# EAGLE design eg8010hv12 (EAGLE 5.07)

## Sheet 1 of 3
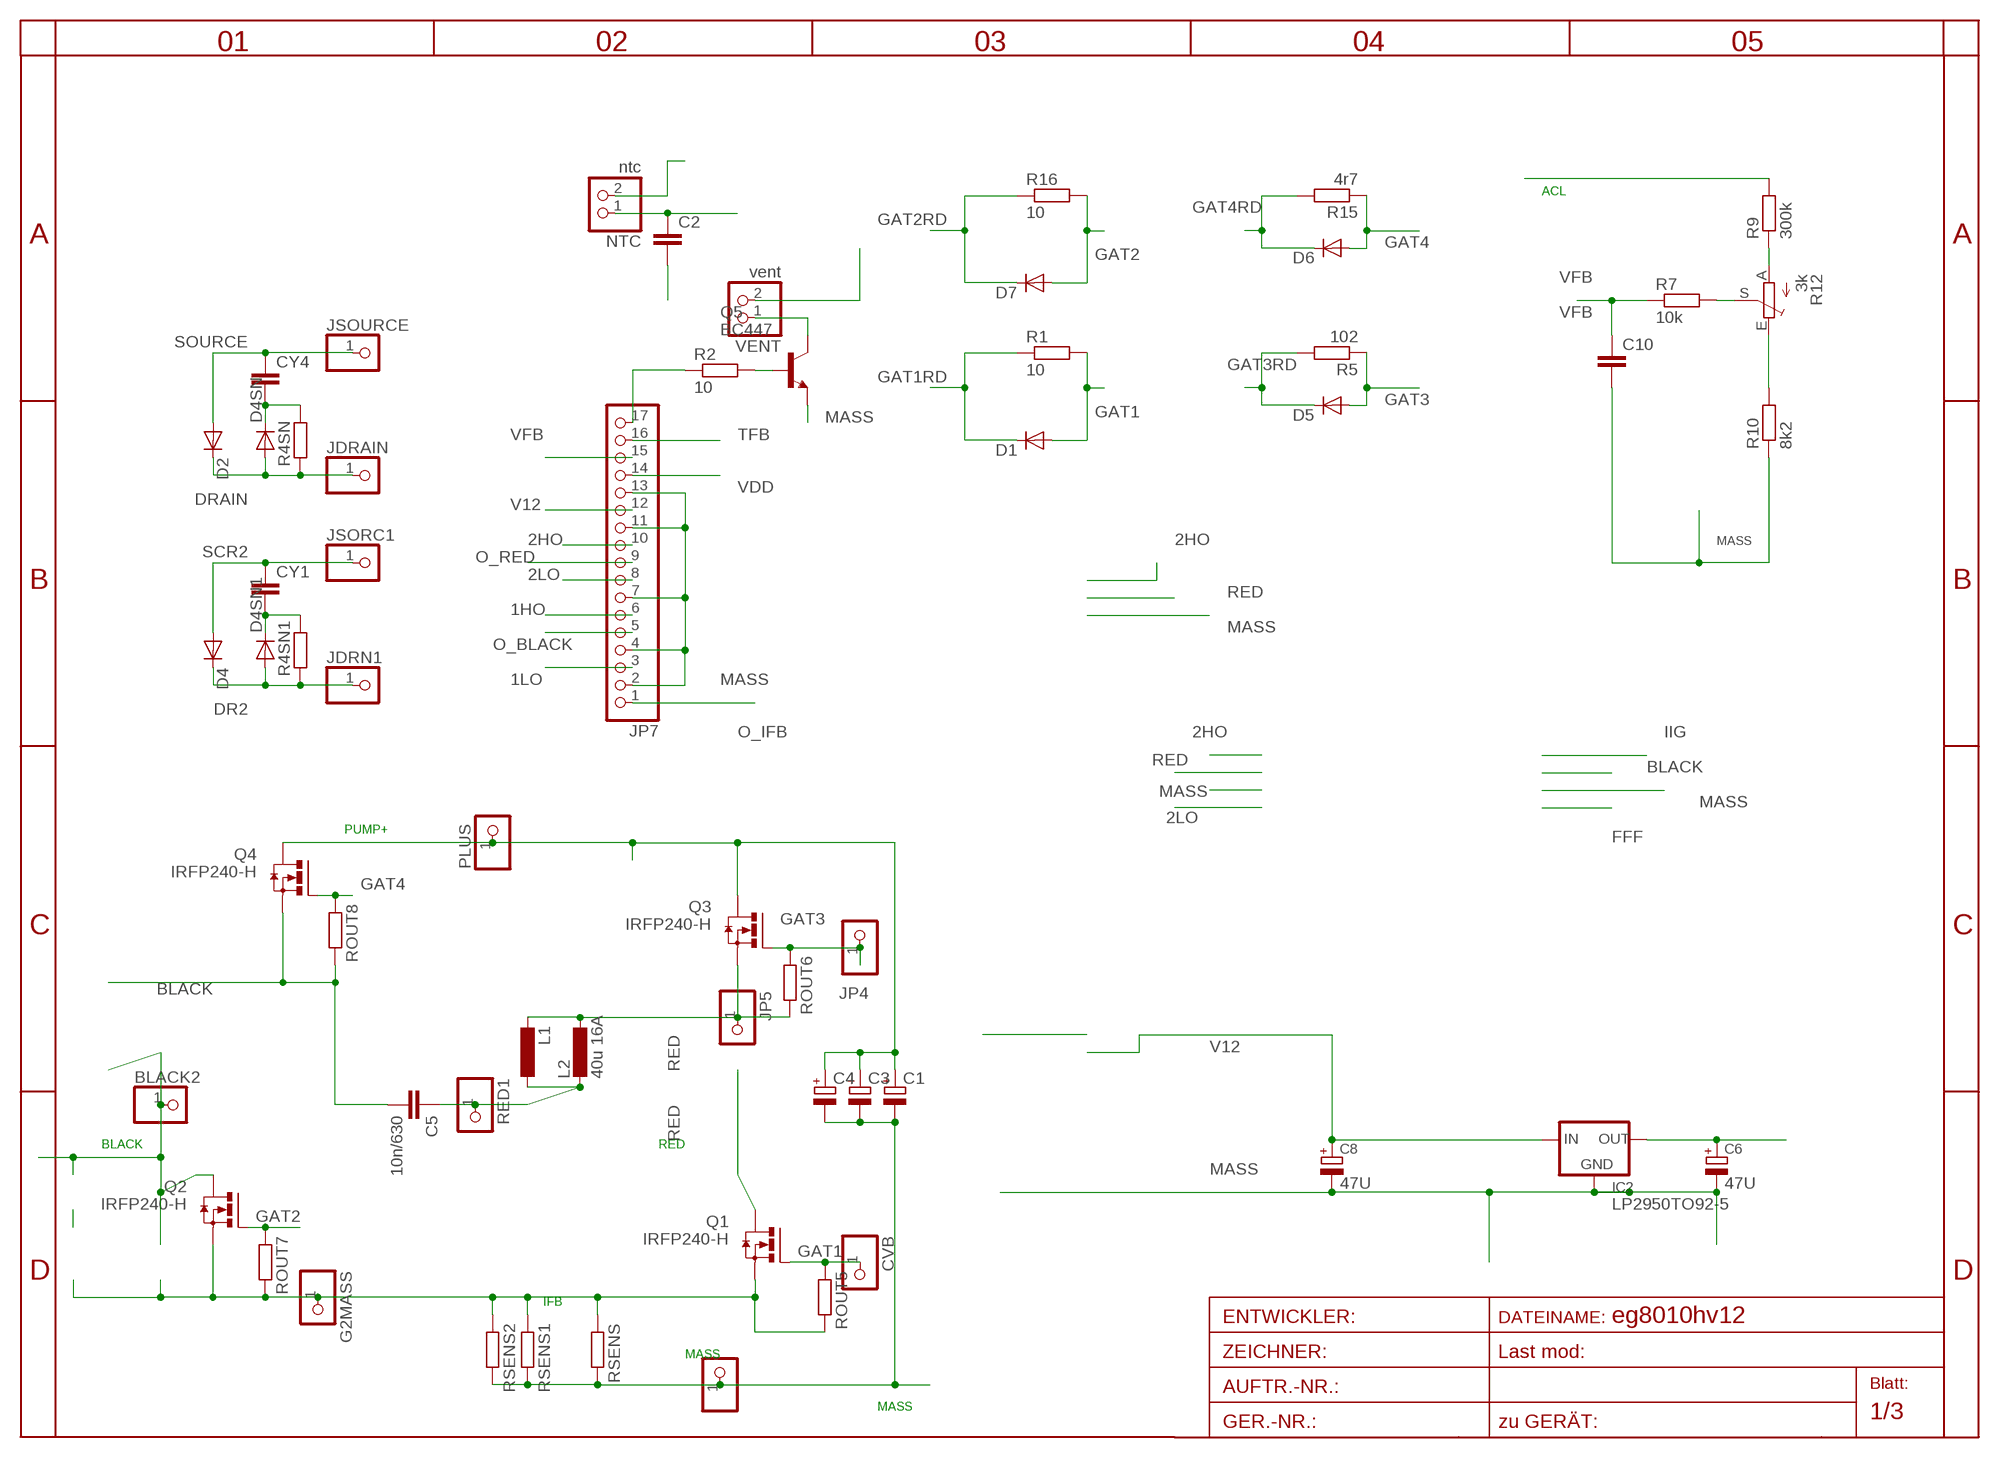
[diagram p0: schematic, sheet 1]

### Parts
BLACK2  PINHD-1X12MM3  [1X2MM3]
C1  CPOL-EUE5-13  [E5-13]
C2  C-EUC1206  [C1206]
C3  CPOL-EUE5-13  [E5-13]
C4  CPOL-EUE5-13  [E5-13]
C5  10n/630  C-EU275-173X316  [C275-173X316]
C6  47U  CPOL-EUE2.5-6  [E2,5-6]
C8  47U  CPOL-EUE2.5-6  [E2,5-6]
C10  C-EUC0805  [C0805]
CVB  PINHD-1X11MM0  [1X1MM0]
CY1  CXXC10B5  [XC10B5]
CY4  CXXC10B5  [XC10B5]
D1  DIODE-SMA-DO214  [SMA-DO214AC]
D2  DIODE-SMC  [SMC]
D4  DIODE-SMC  [SMC]
D4SN  DIODE-P1-10  [P1-10]
D4SN1  DIODE-P1-10  [P1-10]
D5  DIODE-MINIMELF  [MINIMELF]
D6  DIODE-SMA-DO214  [SMA-DO214AC]
D7  DIODE-SMA-DO214  [SMA-DO214AC]
G2MASS  PINHD-1X11MM0  [1X1MM0]
IC2  LP2950TO92-5  [T092-5]
JDRAIN  PINHD-1X11MM0  [1X1MM0]
JDRN1  PINHD-1X11MM0  [1X1MM0]
JP4  PINHD-1X11MM0  [1X1MM0]
JP5  PINHD-1X11MM0  [1X1MM0]
JP7  PINHD-1X17  [1X17]
JSORC1  PINHD-1X11MM0  [1X1MM0]
JSOURCE  PINHD-1X11MM0  [1X1MM0]
L1  L-EU4.13  [0204/13]
L2  40u 16A  L-EURNG  [RING]
MINUS  PINHD-1X12MM3  [1X2MM3]
NTC  ntc  PINHD-1X2STR  [1X02]
PLUS  PINHD-1X12MM3  [1X2MM3]
Q1  IRFP240-H  [TO247BH]
Q2  IRFP240-H  [TO247BH]
Q3  IRFP240-H  [TO247BH]
Q4  IRFP240-H  [TO247BH]
Q5  BC447  [TO92-EBC]
R1  10  R-EU_R1206  [R1206]
R2  10  R-EU_R0805  [R0805]
R4SN  R-EU_0207/10  [0207/10]
R4SN1  R-EU_0207/10  [0207/10]
R5  102  R-EU_R1206  [R1206]
R7  10k  R-EU_R0805  [R0805]
R9  300k  R-EU_0207/40  [0207/40]
R10  8k2  R-EU_R0805  [R0805]
R12  3k  TRIM_EU-CA6V  [CA6V]
R15  4r7  R-EU_0411/15  [0411/15]
R16  10  R-EU_R1206  [R1206]
RED1  PINHD-1X12MM3  [1X2MM3]
ROUT5  R-EU_0207/10  [0207/10]
ROUT6  R-EU_0207/10  [0207/10]
ROUT7  R-EU_0207/10  [0207/10]
ROUT8  R-EU_0207/10  [0207/10]
RSENS  R-EU_0204/7  [0204/7]
RSENS1  R-EU_0204/7  [0204/7]
RSENS2  R-EU_0922V  [0922V]
VENT  vent  PINHD-1X2STR  [1X02]

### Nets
1HO: JP7.6 ; also sheet 3
1LO: JP7.3 ; also sheet 3
2HO: JP7.10 ; also sheet 3
2LO: JP7.8 ; also sheet 3
ACL: C5.1 L1.1 L2.2 R9.2 RED1.1
BLACK: BLACK2.1 C5.2 Q2.D Q4.S ROUT8.2 ; also sheet 3
DR2: D4.C D4SN1.A JDRN1.1 R4SN1.1
DRAIN: D2.C D4SN.A JDRAIN.1 R4SN.1
GAT1: CVB.1 D1.A Q1.G R1.2 ROUT5.1
GAT1RD: D1.K(C) R1.1 ; also sheet 3
GAT2: D7.A Q2.G R16.2 ROUT7.1
GAT2RD: D7.K(C) R16.1 ; also sheet 3
GAT3: D5.A JP4.1 Q3.G R5.1 ROUT6.1
GAT3RD: D5.C R5.2 ; also sheet 3
GAT4: D6.A Q4.G R15.1 ROUT8.1
GAT4RD: D6.K(C) R15.2 ; also sheet 3
IFB: G2MASS.1 Q1.S Q2.S ROUT5.2 ROUT7.2 RSENS1.1 RSENS2.1 RSENS.1 ; also sheet 3
MASS: C1.- C2.2 C3.- C4.- C6.- C8.- C10.2 IC2.2(GND) JP7.2 JP7.4 JP7.7 JP7.11 JP7.13 MINUS.1 Q5.E R10.1 RSENS1.2 RSENS2.2 RSENS.2 ; also sheet 2,3
N$1: Q5.C VENT.1
N$2: Q5.B R2.2
N$3: JP7.17 R2.1
N$29: R10.2 R12.E
N$30: R9.1 R12.A
N$31: R7.2 R12.S
O_BLACK: JP7.5
O_IFB: JP7.1 ; also sheet 3
O_RED: JP7.9
PUMP+: C1.+ C3.+ C4.+ PLUS.1 Q3.D Q4.D ; also sheet 2
RED: JP5.1 L1.2 L2.1 Q1.D Q3.S ROUT6.2 ; also sheet 3
SCR2: CY1.1 D4.A JSORC1.1
SNUB1: CY1.2 D4SN1.C R4SN1.2
SNUB2: CY4.2 D4SN.C R4SN.2
SOURCE: CY4.1 D2.A JSOURCE.1
TFB: C2.1 JP7.16 NTC.1
V12: C8.+ IC2.3(IN) JP7.12 ; also sheet 2,3
VDD: C6.+ IC2.1(OUT) JP7.14 NTC.2 VENT.2
VFB: C10.1 JP7.15 R7.1

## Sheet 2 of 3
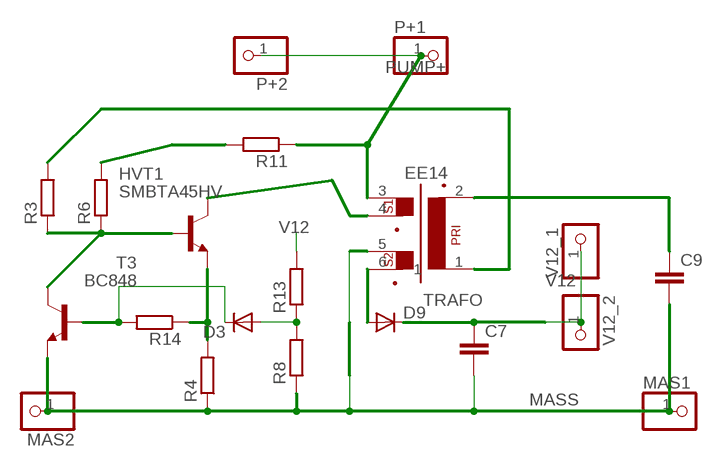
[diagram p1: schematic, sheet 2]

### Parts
C7  C-EUC1206  [C1206]
C9  C-EUC0805  [C0805]
D3  DIODE-MINIMELF  [MINIMELF]
D9  DIODE-SMA-DO214  [SMA-DO214AC]
HVT1  SMBTA45HV  [SOT23HV]
MAS1  PINHD-1X11X0.4  [1X01]
MAS2  PINHD-1X11X0.4  [1X01]
P+1  PINHD-1X11X0.4  [1X01]
P+2  PINHD-1X11X0.4  [1X01]
R3  R-EU_R0805  [R0805]
R4  R-EU_R0805  [R0805]
R6  R-EU_R1206  [R1206]
R8  R-EU_R0805  [R0805]
R11  R-EU_R1206  [R1206]
R13  R-EU_R0805  [R0805]
R14  R-EU_R0805  [R0805]
T3  BC848  [SOT23]
TRAFO  EE14  [EE14]
V12_1  PINHD-1X11X0.4  [1X01]
V12_2  PINHD-1X11X0.4  [1X01]

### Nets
A: D9.A TRAFO.6
B1C2: HVT1.1(B) R3.1 R6.1 T3.C
BT1: D3.C R14.2 T3.B
C1: HVT1.3(C) TRAFO.4
EB: HVT1.2(E) R4.2 R14.1
MASS: C7.2 C9.2 MAS1.1 MAS2.1 R4.1 R8.1 T3.E TRAFO.5 ; also sheet 1,3
N$6: R3.2 TRAFO.1
N$7: C9.1 TRAFO.2
N$8: R6.2 R11.2
N$10: D3.A R8.2 R13.1
PUMP+: P+1.1 P+2.1 R11.1 TRAFO.3 ; also sheet 1
V12: C7.1 D9.K(C) R13.2 V12_1.1 V12_2.1 ; also sheet 1,3

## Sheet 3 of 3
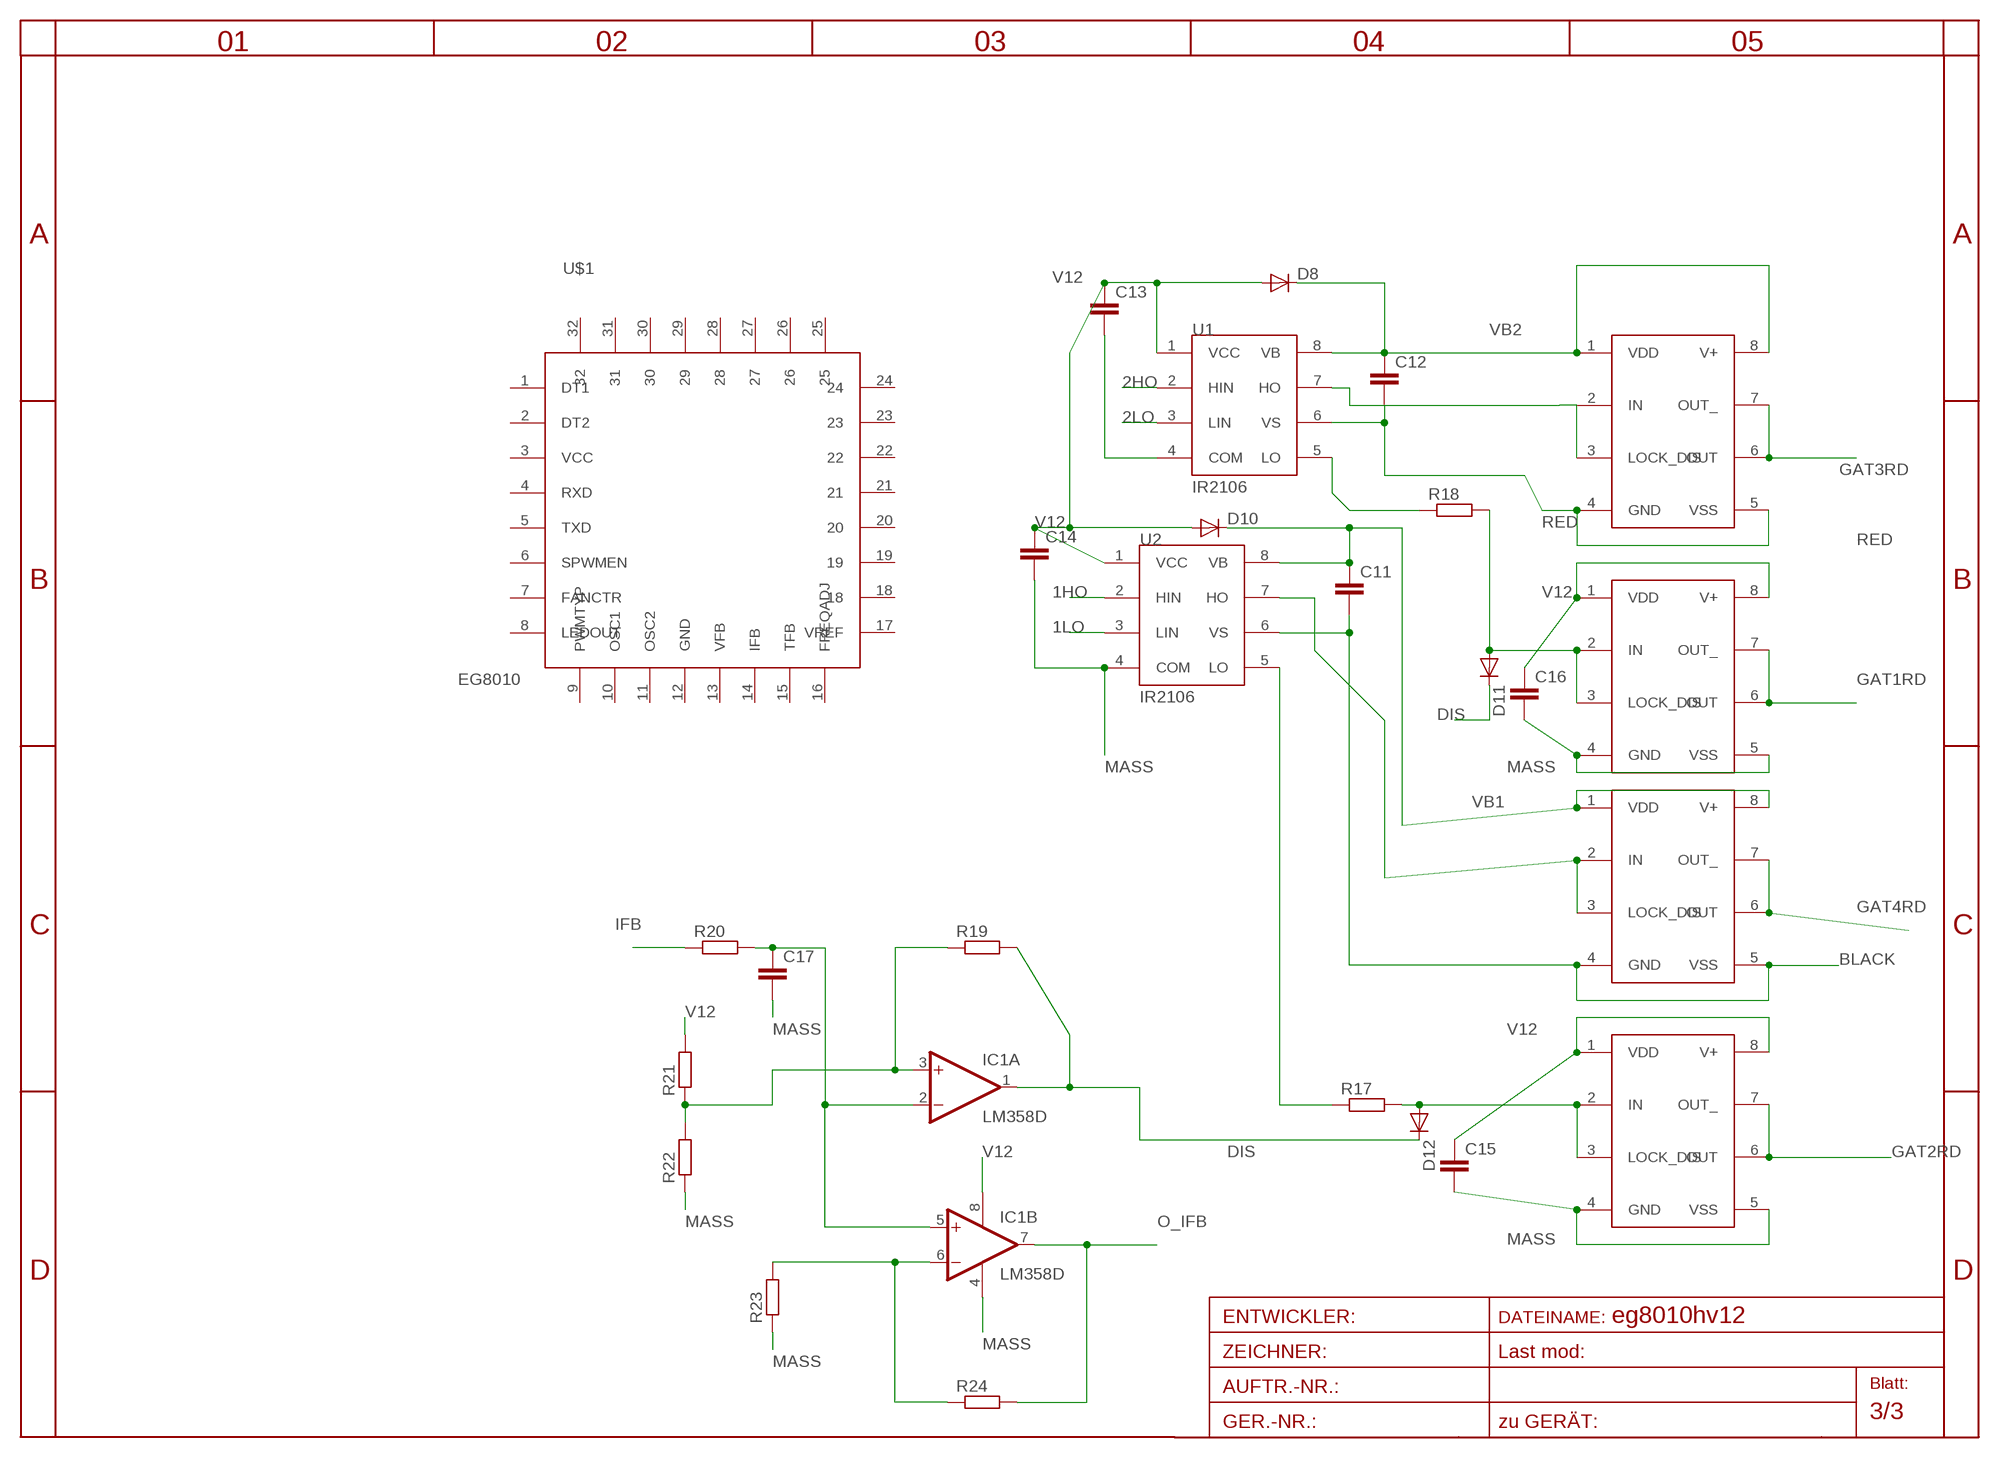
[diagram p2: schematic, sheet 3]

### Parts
1HDRV  TC4432X  [SO-08]
1LODRV  TC4432X  [SO-08]
2HDRV  TC4432X  [SO-08]
2LODRV  TC4432X  [SO-08]
C11  C-EUC1206  [C1206]
C12  C-EUC1206  [C1206]
C13  C-EUC1206  [C1206]
C14  C-EUC1206  [C1206]
C15  C-EUC1206  [C1206]
C16  C-EUC1206  [C1206]
C17  C-EUC1206  [C1206]
D8  DIODE-SMA-DO214  [SMA-DO214AC]
D10  DIODE-SMA-DO214  [SMA-DO214AC]
D11  DIODE-SOT23  [SOT23]
D12  DIODE-SOT23  [SOT23]
IC1  LM358D  [SO08]
R17  R-EU_0207/20  [0207/20]
R18  R-EU_0204/7  [0204/7]
R19  R-EU_R1206  [R1206]
R20  R-EU_R0805  [R0805]
R21  R-EU_R0805  [R0805]
R22  R-EU_R0805  [R0805]
R23  R-EU_R0805  [R0805]
R24  R-EU_R0805  [R0805]
U1  IR2106  [SO8-2]
U2  IR2106  [SO8-2]
U$1  EG8010  [EG8010-32]

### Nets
1HO: U2.2(HIN) ; also sheet 1
1LO: U2.3(LIN) ; also sheet 1
2HO: U1.2(HIN) ; also sheet 1
2LO: U1.3(LIN) ; also sheet 1
BLACK: 1HDRV.4(GND) 1HDRV.5(VSS) C11.2 U2.6(VS) ; also sheet 1
DIS: D11.3(C) D12.3(C) IC1.1(A:OUT) R19.2
GAT1RD: 2LODRV.6(OUT) 2LODRV.7(OUT_) ; also sheet 1
GAT2RD: 1LODRV.6(OUT) 1LODRV.7(OUT_) ; also sheet 1
GAT3RD: 2HDRV.6(OUT) 2HDRV.7(OUT_) ; also sheet 1
GAT4RD: 1HDRV.6(OUT) 1HDRV.7(OUT_) ; also sheet 1
IFB: R20.1 ; also sheet 1
MASS: 1LODRV.4(GND) 1LODRV.5(VSS) 2LODRV.4(GND) 2LODRV.5(VSS) C13.2 C14.2 C15.2 C16.2 C17.2 IC1.4(P:V-) R22.1 R23.1 U1.4(COM) U2.4(COM) ; also sheet 1,2
N$4: R18.1 U1.5(LO)
N$5: 1LODRV.2(IN) 1LODRV.3(LOCK_DIS) D12.1(A) R17.2
N$9: IC1.3(A:+IN) R19.1 R21.1 R22.2
N$11: R17.1 U2.5(LO)
N$12: 2HDRV.2(IN) 2HDRV.3(LOCK_DIS) U1.7(HO)
N$13: 1HDRV.2(IN) 1HDRV.3(LOCK_DIS) U2.7(HO)
N$15: C17.1 IC1.2(A:-IN) IC1.5(B:+IN) R20.2
N$16: 2LODRV.2(IN) 2LODRV.3(LOCK_DIS) D11.1(A) R18.2
N$18: IC1.6(B:-IN) R23.2 R24.1
O_IFB: IC1.7(B:OUT) R24.2 ; also sheet 1
RED: 2HDRV.4(GND) 2HDRV.5(VSS) C12.2 U1.6(VS) ; also sheet 1
V12: 1LODRV.1(VDD) 1LODRV.8(V+) 2LODRV.1(VDD) 2LODRV.8(V+) C13.1 C14.1 C15.1 C16.1 D8.A D10.A IC1.8(P:V+) R21.2 U1.1(VCC) U2.1(VCC) ; also sheet 1,2
VB1: 1HDRV.1(VDD) 1HDRV.8(V+) C11.1 D10.K(C) U2.8(VB)
VB2: 2HDRV.1(VDD) 2HDRV.8(V+) C12.1 D8.K(C) U1.8(VB)
Unconnected: U$1.1(DT1) U$1.2(DT2) U$1.4(RXD) U$1.5(TXD) U$1.6(SPWMEN) U$1.8(LEDOUT) U$1.9(PWMTYP) U$1.10(OSC1) U$1.11(OSC2) U$1.12(GND) U$1.13(VFB) U$1.14(IFB) U$1.15(TFB) U$1.16(FREQADJ) U$1.17(VREF) U$1.18 U$1.19 U$1.20 U$1.21 U$1.22 U$1.23 U$1.24 U$1.26 U$1.27 U$1.29 U$1.30 U$1.31 U$1.32

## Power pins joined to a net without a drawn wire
25: U$1.25
28: U$1.28
FANCTR: U$1.7(FANCTR)
VCC: U$1.3(VCC)

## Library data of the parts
1HDRV 1LODRV 2HDRV 2LODRV = microchip:TC4432
BLACK2 CVB G2MASS JDRAIN JDRN1 JP4 JP5 JSORC1 JSOURCE MAS1 MAS2 MINUS P+1 P+2 PLUS RED1 V12_1 V12_2 = pinhead:PINHD-1X1: PIN HEADER
C1 C3 C4 = rcl:CPOL-EU: POLARIZED CAPACITOR, European symbol
C2 C5 C7 C9-C17 = rcl:C-EU: CAPACITOR, European symbol
C6 C8 = rcl-2:CPOL-EU: POLARIZED CAPACITOR, European symbol
CY1 CY4 = rcl:CX: X CAPACITOR
D1-D4 D4SN D4SN1 D5-D12 = diode:DIODE-: DIODE
HVT1 = transistor-npn:SMBTA45
IC1 = linear:LM358: OP AMP also LM158; LM258; LM2904 Source: http://cache.national.com/ds/LM/LM158.pdf
IC2 = v-reg:LP2950?*: Source: http://cache.national.com/ds/LP/LP2950.pdf
JP7 = pinhead:PINHD-1X17: PIN HEADER
L1 L2 = rcl:L-EU: INDUCTOR, European symbol
NTC VENT = pinhead:PINHD-1X2: PIN HEADER
Q1-Q4 = transistor-power:IRFP240: HEXFET Power MosFet Source: http://www.irf.com/
Q5 = transistor-npn:BC447*: NPN Transistor
R1-R4 R4SN R4SN1 R5 R6 R8 R11 R13-R16 R18-R24 ROUT5-ROUT8 RSENS RSENS1 RSENS2 = rcl:R-EU_: RESISTOR, European symbol
R7 R9 R10 R17 = rcl-2:R-EU_: RESISTOR, European symbol
R12 = pot:TRIM_EU-: POTENTIOMETER
T3 = transistor:BC848: NPN TRANSISTOR
TRAFO = trafo:EE14
U1 U2 = irf-2:IR2106
U$1 = texas:EG8010

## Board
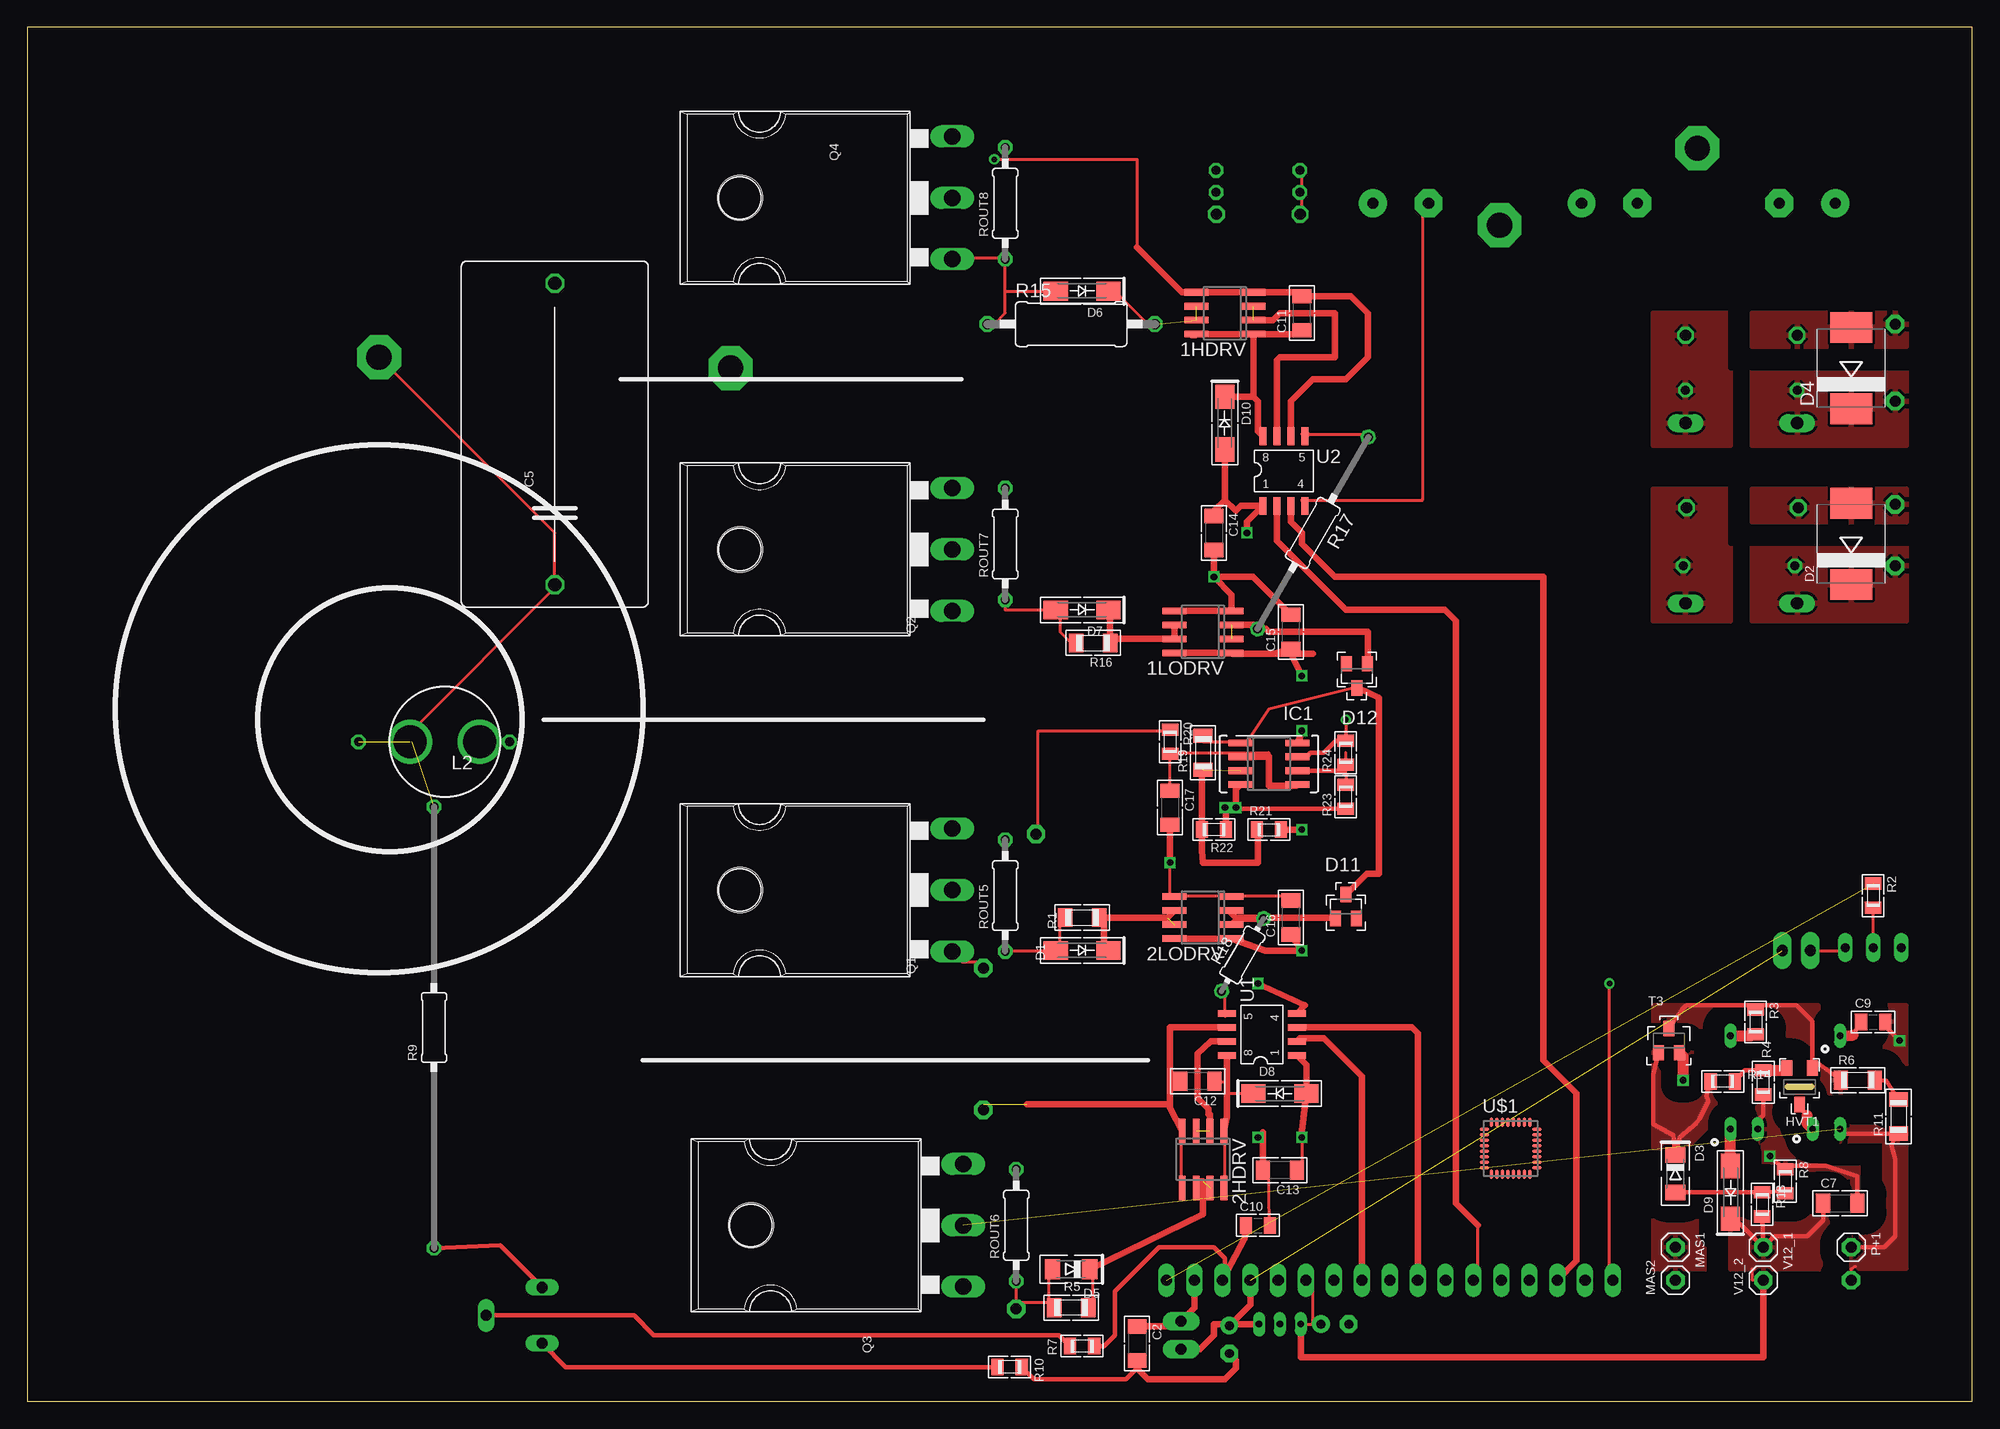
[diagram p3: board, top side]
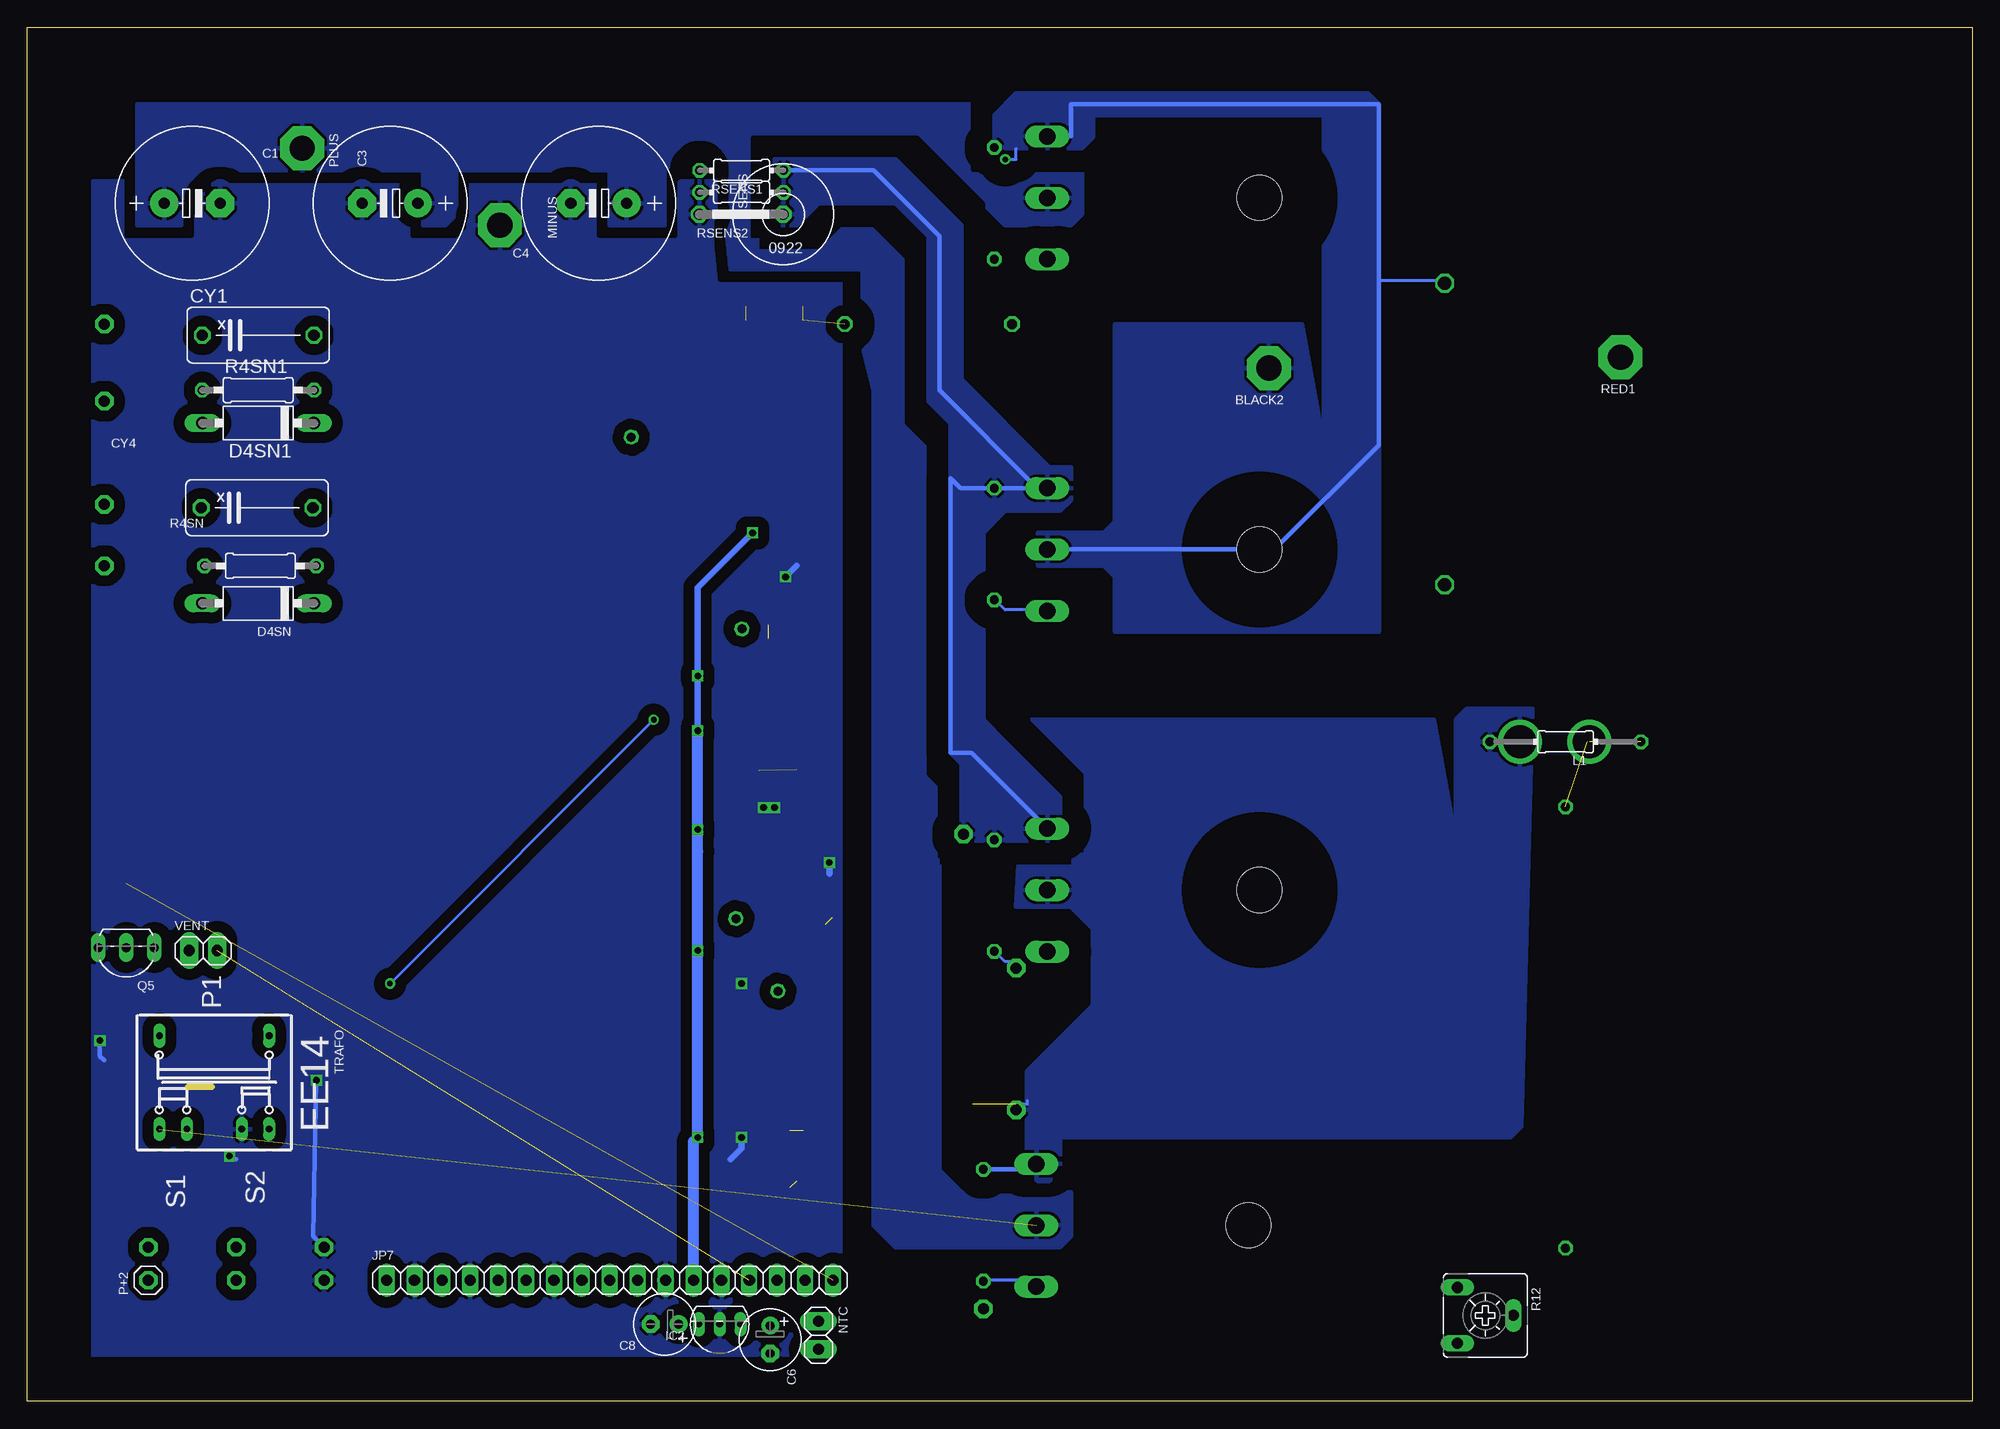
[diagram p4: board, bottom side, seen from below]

Size 177 x 125 mm. Coordinates in mm from the lower left corner, seen from the top.
Outline: 0,0 177,0 177,125 0,125 0,0
Copper layers (1*16): Top 0.035mm / dielectric 1.5mm / Bottom 0.035mm
Design rules "default *": minimum track width 10mil, minimum drill 20mil, track to track 8mil, track to pad 8mil, pad to pad 8mil, via to via 8mil, smd to smd 8mil, copper to edge 4mm, drill to drill 8mil, minimum pad ring 10mil, minimum via ring 8mil, stop-mask expansion 4mil, vias tented up to drill 0mil, thermal gap 10mil

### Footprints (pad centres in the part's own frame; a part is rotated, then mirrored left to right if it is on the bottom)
SO-08 = smd 0.6 x 2.2: 1 -1.905,-2.6; 2 -0.635,-2.6; 3 0.635,-2.6; 4 1.905,-2.6; 5 1.905,2.6; 6 0.635,2.6; 7 -0.635,2.6; 8 -1.905,2.6
1X2MM3 = drill 2.3 pad 4 octagon: 1 0,0
E5-13 = drill 1.016 pad 2.54 round: + -2.54,0 | drill 1.016 pad 2.54 octagon: - 2.54,0
C1206 = smd 1.3 x 1.7: 1 -1.55,0; 2 1.55,0
C275-173X316 = drill 1.194 octagon: 1 -13.716,0; 2 13.716,0
E2,5-6 = drill 0.813 pad 1.6 round: + -1.27,0 | drill 0.813 pad 1.6 octagon: - 1.27,0
C0805 = smd 1.1 x 1.5: 1 -1.1,0; 2 1.1,0
1X1MM0 = drill 1 pad 1.676 octagon: 1 0,0
XC10B5 = drill 1.016 octagon: 1 -5.08,0; 2 5.08,0
SMA-DO214AC = smd 2.2 x 1.7: A 2.4,0; K -2.4,0
SMC = smd 2.8 x 3.8: A 3.7,0; C -3.7,0
MINIMELF = smd 1.4 x 1.8: A 1.7,0; C -1.7,0
P1-10 = drill 1.118 long: A 5.08,0; C -5.08,0
SOT23 = smd 1 x 1.4: 1 -0.95,-1.1; 2 0.95,-1.1; 3 0,1.1
SOT23HV = smd 1 x 1.4: 1 -1.15,-1.7; 2 1.15,-1.7; 3 0,1.6
SO08 = smd 0.6 x 2.2: 1 -1.905,-2.6; 2 -0.635,-2.6; 3 0.635,-2.6; 4 1.905,-2.6; 5 1.905,2.6; 6 0.635,2.6; 7 -0.635,2.6; 8 -1.905,2.6
T092-5 = drill 0.6 pad 0.813 long: 1 -1.905,0; 2 0,0; 3 1.905,0
1X17 = drill 1.016 long: 1 -20.32,0; 2 -17.78,0; 3 -15.24,0; 4 -12.7,0; 5 -10.16,0; 6 -7.62,0; 7 -5.08,0; 8 -2.54,0; 9 0,0; 10 2.54,0; 11 5.08,0; 12 7.62,0; 13 10.16,0; 14 12.7,0; 15 15.24,0; 16 17.78,0; 17 20.32,0
0204/13 = drill 0.813 octagon: 1 -6.872,0; 2 6.872,0
RING = drill 3 pad 4 round: 1 -3.15,0; 2 3.15,0
1X01 = drill 1 pad 1.676 octagon: 1 0,0
1X02 = drill 1.016 pad 1.676 long: 1 -1.27,0; 2 1.27,0
TO247BH = drill 1.499 long: D 0,-10.16; G -5.588,-10.16; S 5.588,-10.16 | hole 4.115: 0,9.144
TO92-EBC = drill 0.813 long: B 0,-1.27; C -2.54,-1.27; E 2.54,-1.27
R1206 = smd 1.3 x 1.7: 1 -1.55,0; 2 1.55,0
R0805 = smd 1.1 x 1.5: 1 -1.1,0; 2 1.1,0
0207/10 = drill 0.813 octagon: 1 -5.08,0; 2 5.08,0
0207/40 = drill 0.813 octagon: 1 -20.08,0; 2 20.08,0
CA6V = drill 1.016 long: A -2.54,-2.54; E 2.54,-2.54; S 0,2.54
0411/15 = drill 0.914 octagon: 1 -7.62,0; 2 7.62,0
0207/20 = drill 0.813 octagon: 1 -10.08,0; 2 10.08,0
0204/7 = drill 0.813 octagon: 1 -3.81,0; 2 3.81,0
0922V = drill 1.016 octagon: 1 -5.08,0; 2 2.54,0
SOT23' = smd 1 x 1.4: B -0.95,-1.1; C 0,1.1; E 0.95,-1.1
EE14 = drill 0.6 pad 1 long: 1 4.25,-5; 2 4.25,5; 3 -4.25,5 | drill 0.6 pad 1.016 long: 4 -4.25,2.5; 5 -4.25,-2.5; 6 -4.25,-5
SO8-2 = smd 0.61 x 1.626: 1 -2.54,-2.54; 2 -1.27,-2.54; 3 0,-2.54; 4 1.27,-2.54; 5 1.27,3.81; 6 0,3.81; 7 -1.27,3.81; 8 -2.54,3.81
EG8010-32 = smd 0.85 x 0.3: 1 -2.375,1.75; 2 -2.375,1.25; 3 -2.375,0.75; 4 -2.375,0.25; 5 -2.375,-0.25; 6 -2.375,-0.75; 7 -2.375,-1.25; 8 -2.375,-1.75; 17 2.375,-1.75; 18 2.375,-1.25; 19 2.375,-0.75; 20 2.375,-0.25; 21 2.375,0.25; 22 2.375,0.75; 23 2.375,1.25; 24 2.375,1.75 | smd 0.3 x 0.85: 9 -1.75,-2.375; 10 -1.25,-2.375; 11 -0.75,-2.375; 12 -0.25,-2.375; 13 0.25,-2.375; 14 0.75,-2.375; 15 1.25,-2.375; 16 1.75,-2.375; 25 1.75,2.375; 26 1.25,2.375; 27 0.75,2.375; 28 0.25,2.375; 29 -0.25,2.375; 30 -0.75,2.375; 31 -1.25,2.375; 32 -1.75,2.375

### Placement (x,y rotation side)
1HDRV  109,99 90 top
1LODRV  107,70 90 top
2HDRV  107,22 180 top
2LODRV  107,44 90 top
BLACK2  64,94 180 bottom
C1  162,109 0 bottom
C2  101,5.25 270 top
C3  144,109 180 bottom
C4  125,109 180 bottom
C5  48,88 90 top
C6  109.4,5.6 270 bottom
C7  165,18 0 top
C8  119,7 180 bottom
C9  168,34.5 0 top
C10  112,16 0 top
C11  116,99 90 top
C12  106.5,29.1 180 top
C13  114,21 180 top
C14  108,79 270 top
C15  115,70 90 top
C16  115,44 90 top
C17  104,54 270 top
CVB  87,39.4 270 bottom
CY1  156,97 0 bottom
CY4  156.1,81.3 0 bottom
D1  96,41 180 top
D2  166,78 90 top
D3  150,20.7 270 top
D4  166,94 90 top
D4SN  156,72.6 180 bottom
D4SN1  156,89 180 bottom
D5  95,12 180 top
D6  96,101 180 top
D7  96,72 180 top
D8  114,28 0 top
D9  155,19 90 top
D10  109,89 270 top
D11  120,45 0 top
D12  121,66 180 top
G2MASS  91.8,51.6 270 bottom
HVT1  161.3,28.6 180 top
IC1  113,58 270 top
IC2  114,7 180 bottom
JDRAIN  170,76 270 top
JDRN1  170,91 0 top
JP4  90,8.4 90 bottom
JP5  87,26.5 90 bottom
JP7  124,11 0 bottom
JSORC1  170,98 0 top
JSOURCE  170,81.6 270 top
L1  37,60 180 bottom
L2  38,60 180 top
MAS1  150,14 270 top
MAS2  150,11 90 top
MINUS  134,107 270 bottom
NTC  105,6 270 bottom
P+1  166,14 270 top
P+2  166,11 90 bottom
PLUS  152,114 270 bottom
Q1  74,46.5 90 top
Q2  74,77.5 90 top
Q3  75,16 90 top
Q4  74,109.5 90 top
Q5  168,40 180 bottom
R1  96,44 180 top
R2  168,46 270 top
R3  157.3,34.5 270 top
R4  158,29 90 top
R4SN  155.8,76 0 bottom
R4SN1  156,92 0 bottom
R5  95,8.5 0 top
R6  166.6,29.2 0 top
R7  96,5 180 top
R8  160,20 270 top
R9  37,34 90 top
R10  89.4,3.1 180 top
R11  170.3,25.9 90 top
R12  44.3,7.8 270 bottom
R13  157.9,17.9 270 top
R14  154.3,29.1 180 top
R15  95,98 0 top
R16  97,69 180 top
R17  117,79 240 top
R18  110.6,40.6 60 top
R19  107,59 90 top
R20  104,60 270 top
R21  113,52 0 top
R22  108,52 180 top
R23  120,55 90 top
R24  120,59 90 top
RED1  32,95 180 bottom
ROUT5  89,46 90 top
ROUT6  90,16 90 top
ROUT7  89,78 90 top
ROUT8  89,109 90 top
RSENS  112,110 180 bottom
RSENS1  112,112 180 bottom
RSENS2  113.3,108 180 bottom
T3  BC848  [SOT23']  149.4,32.8 0 top
TRAFO  160,29 90 bottom
U1  113,34 90 top
U2  115,84 0 top
U$1  135,23 0 top
V12_1  158,14 270 top
V12_2  158,11 90 top
VENT  161,41 0 bottom

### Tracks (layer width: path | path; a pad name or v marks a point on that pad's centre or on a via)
1HO
  Top 0.254: 132,16 132,11 JP7.6
  Top 0.6: 132,16 130,18 130,71 129,72 120,72 113.73,78.27 U2.2
1LO
  Top 0.6: JP7.3 141,12.76 141,28 138,31 138,75 119,75 116,78 116,79 115,80 U2.3
2HO
  Top 0.6: U1.2 115.81,33 118,33 121.46,29.54 JP7.10
2LO
  Top 0.6: U1.3 126,34 126.54,33.46 JP7.8
A
  Top 1: D9.A TRAFO.6
ACL  (2 unrouted)
  Top 0.254: L1.1 30,60 | L2.2 35,60 35,61 48,74 C5.1 48,79 RED1.1
B1C2
  Top 0.406: R6.1 163.05,30.7 HVT1.1 162.45,34.55 161,36 157.9,36 | 157.7,36 R3.1 157.9,36 | T3.C 150.6,35.6 151,36 157.7,36 | 157.7,36 157.9,36
  pour Top (isolate 2): 163,31 163,36 148,36 148,33 161,33 161,31 164,28 166,28 166,30
BLACK  (via drill 0.51)
  Top 0.254: v88,113 101,113 101,105
  Top 0.6: 101,105 105.09,100.91 1HDRV.5 1HDRV.4 115.64,100.91 C11.2 120.45,100.55 122,99 122,95 120,93 117,93 115,91 U2.6
  Bottom 0.254: 54,102 48,102 C5.2 | 87,114 87,113 v88,113
  Bottom 0.406: Q4.S 82,115.09 82,118 54,118 54,102 54,87 63.5,77.5 Q2.D
  pour Bottom (isolate 2): 89,117 89,114 81,114 80,115 80,117 59,117 59,87 61,98 78,98 78,80 79,79 85,79 85,76 79,76 78,75 78,70 54,70 54,118 55,119 87,119
BT1
  Top 0.406: T3.B 148,29.75 148,25.2 149.8,24.2 D3.C 150.4,24 151.9,25.3 152.2,25.7 153,27.3 152.8,27.8 R14.2
  pour Top (isolate 1.5, rank 2): 155,29 155,27 151,23 148,23 148,32 150,32 150,31 152,29
C1
  Top 0.406: HVT1.3 161.3,26.7 162,26
  Top 1: 162,26 162,25.25 TRAFO.4
DIS
  Top 0.254: R19.2 107,60 110,60 IC1.1 111,60 113,63 121,65 D12.3
  Top 0.6: D11.3 121.9,48 123,48 123,64 121.1,64.9 D12.3
DR2
  pour Top (isolate 2, rank 2): 171,94 157,94 157,87 171,87
DRAIN
  pour Top (isolate 2, rank 2): 171,78 157,78 157,71 171,71
EB
  Top 0.406: R14.1 156.3,30.1 R4.2 | 159.95,30.1 HVT1.2
  Top 1: R4.2 159.95,30.1
GAT1
  Top 0.254: R1.2 94,44 94,41 D1.A 89,41 ROUT5.1 | Q1.G 85,40 87,40 CVB.1
  Bottom 0.254: ROUT5.1 89,41 88,40 87,40 CVB.1
GAT1RD  (1 unrouted)
  Top 0.6: 2LODRV.6 103.77,44 98,44 | 98,44 R1.1 | D1.K 98,41.4 98,44
GAT2
  Top 0.254: R16.2 95,69 94,70 94,72 D7.A 89,72 ROUT7.1 89,73
  Bottom 0.254: ROUT7.1 89,73 88,72 85,72 Q2.G
GAT2RD
  Top 0.6: 1LODRV.6 1LODRV.7 98.92,69.36 R16.1 98.55,71.85 D7.K
GAT3
  Top 0.254: 90,9 93,9 | 93,9 93,12 D5.A | 93,9 R5.1 | 90,9 ROUT6.1 90,11 | 90,9 JP4.1
  Bottom 0.254: Q3.G 86,11 90,11 ROUT6.1
GAT3RD  (1 unrouted)
  Top 0.254: R5.2 97,9 97,12 D5.C
  Top 0.6: D5.C 107,17 107,20 106.77,20 2HDRV.6
GAT4
  Top 0.254: 89,101 ROUT8.1 89,104 85,104 Q4.G | 89,101 D6.A | 89,101 89,99 88,98 R15.1
GAT4RD  (2 unrouted)
  Top 0.254: D6.K 99,101 102,98 R15.2
IFB
  Top 0.254: R20.1 104,61 92,61 92,52 G2MASS.1
  Bottom 0.406: RSENS.1 108.19,109.59 | Q1.S 91.07,59 93,59 93,84 92.08,83.08 ROUT7.2 Q2.S 85.09,83.09 94,92 94,106 100,112 RSENS1.1
  pour Bottom (isolate 2): 109,113 109,107 107,107 105,109 98,109 95,106 95,91 93,89 93,59 92,58 92,51 84,51 83,52 83,55 88,60 90,62 90,79 88,81 83,81 82,82 82,85 84,85 92,93 92,107 98,113 107,113
MASS  (via drill 0.6)
  Top 0.254: C16.2 115,46 110,46 2LODRV.4 109,46 105,46 2LODRV.5 104,46 v104,49 | 116,110 116,112 RSENS1.2 | C10.2 113,18 113,21 C13.2 | U2.4 116,82 127,82 127,109 C4.- | 116,110 116,108 RSENS2.2 | 116,110 RSENS.2
  Top 0.406: C7.2 166.55,20.45 163.7,21.4 160.8,21.4 R8.1 159.9,21.1 v158.6,22.3 | C9.2 169.1,34.1 v170.4,32.8 | TRAFO.5 157.5,25.5 158,26 R4.1 | R23.1 110.1,53.9 v110,54 | 101,3 100,2 91.6,2 R10.1
  Top 0.6: v108,75 109.6,73.4 1LODRV.4 1LODRV.5 | v108,75 C14.2 | C13.2 112.45,24.45 v112,24 | U1.4 116.27,36 v112,38 | C15.2 111.55,75 v108,75 | IC1.4 110,55.7 v110,54 | v109,54 109.1,53.9 R22.1 | v104,49 C17.2 | C2.2 101,3 102,2 109,2 110,3 110,3.73 C6.-
  Top 1: v150.7,29.2 150.7,31.35 T3.E
  Bottom 0.254: RSENS2.2 116,108 115.89,107.73
  Bottom 0.406: v150.7,29.2 151,15 MAS1.1 | v170.4,32.8 170.4,31.4 170,31 | v158.6,22.3 158,22
  Bottom 0.6: v108,75 107,76 | v112,24 112,23 113,22 | v109,54 v110,54 | v104,49 104,48
  pour Bottom (isolate 2): 171,36 171,12 148,12 148,36
  pour Top (isolate 2, rank 5): 171,36 171,12 148,12 148,36
  pour Bottom (isolate 1, rank 4): 103,111 171,111 171,3 104,3 103,12
N$1
  Top 0.254: Q5.C 165,41 VENT.1
N$2
  Top 0.254: 168,45 R2.2 Q5.B
N$3  (1 unrouted)
N$4
  Top 0.254: U1.5 109,35 109,37 R18.1
N$5  (1 unrouted)
  Top 0.6: D12.1 122,67.15 122,70 113,70 112.73,70.27 R17.2 111.59,70.64 1LODRV.3
N$6
  Top 0.406: 156.95,33.25 R3.2
  Top 1: TRAFO.1 156.95,33.25
N$7
  Top 0.406: 166.15,33.3 C9.1
  Top 1: TRAFO.2 166.15,33.3
N$8
  Top 0.406: R11.2 169.2,29.15 R6.2
N$9  (1 unrouted)
  Top 0.6: R21.1 112,51.9 112,49 107,49 106.9,50.1 R22.2 106.9,57.35 R19.1
N$10
  Top 0.406: R8.2 159.8,19.1 R13.1 D3.A
N$11
  Top 0.254: U2.5 116,88 122,88 R17.1
  Top 0.6: U2.5 116.46,88
N$12  (1 unrouted)
  Top 0.6: U1.7 107.73,32.73 106.5,31.6 106.5,27.6 107.5,26.6 107.5,26.1 107.64,26.1 2HDRV.2
N$13  (1 unrouted)
  Top 0.6: 1HDRV.2 113.36,98.36 114,99 119,99 119,95 114,95 113.73,94.73 U2.7
N$15
  Top 0.254: C17.1 R20.2 104,59 113,59 113,58
  Top 0.6: IC1.5 115.5,56 113,56 113,58 113,58.7 112.94,58.63 IC1.2
N$16
  Top 0.6: D11.1 118.95,44 110,44 | 110,44 109.6,44.4 2LODRV.3 | 110,44 110.1,43.9 | 110.1,43.9 R18.2 | 2LODRV.2 110.1,43.87 110.1,43.9
N$18
  Top 0.254: R23.2 120,57 R24.1 120,59
  Top 0.406: IC1.6 119.64,57.37 120,57
N$29
  Top 0.406: R10.2 49,3.1 R12.E
N$30
  Top 0.406: R9.1 43,14.18 R12.A
N$31
  Top 0.406: R12.S 55.2,7.8 57,6 93.9,6 R7.2
O_IFB  (via drill 0.51)
  Top 0.254: v120,62 R24.2 120,61 | v144,38 144,11 JP7.1
  Top 0.406: R24.2 119.1,60.1 118,59 116.8,59 116.5,58.7 115.67,58.7 IC1.7
  Bottom 0.254: v144,38 v120,62
PUMP+  (1 unrouted)
  Top 0.254: P+2.1 166,12 166.38,12.27
  Top 0.406: P+1.1 169,14 170,15 170,22 169.65,23.35 R11.1 165.4,24.35 TRAFO.3
  pour Top (isolate 2, rank 2): 171,25 171,12 166,12 166,16 169,16 169,23.6 165,23.6 165,25
  pour Bottom (isolate 2, rank 3): 82,19 82,15 83,14 98,14 100,16 100,92 101,96 101,103 113,103 114,113 118,113 119,112 119,107 124,107 124,112 138,112 138,108 139,107 141,107 141,112 160,112 163,109 163,107 167,107 167,118 87,118 81,112 81,108 82,107 88,107 93,112 110,112 110,110 107,107 96,107 94,105 94,21 92,19
RED  (1 unrouted)
  Top 0.254: 104,29 105,29 C12.2 | 2HDRV.4 105,24 105,20 2HDRV.5
  Top 0.6: U1.6 104,34 104,29 104,27 | 104,27 104,26.7 2HDRV.4 | 91,27 104,27
  Bottom 0.254: JP5.1 87,27 86,27 86,27.33
  Bottom 0.406: Q3.S 85.67,21.08 ROUT6.2
  pour Bottom (isolate 2, rank 3): 40,63 46,63 47,62 47,51 49,62 86,62 87,45 82,45 80,43 80,36 86,30 86,21 85,20 84,20 83,21 83,24 42,24 41,25
SCR2
  pour Top (isolate 2): 171,99 171,96 157,96 157,99
SNUB1
  pour Top (isolate 2, rank 2): 155,99 155,87 148,87 148,99
SNUB2
  pour Top (isolate 2, rank 2): 155,83 155,71 148,71 148,83
SOURCE
  pour Top (isolate 2): 171,83 171,80 157,80 157,83
TFB
  Top 0.6: C2.1 104.53,6.8 NTC.1 106.22,8.49 JP7.16
V12  (via drill 0.6)
  Top 0.254: 114,52 R21.2 | v116,24 116,21 C13.1 | IC2.3 117,7 | V12_2.1 157,11 157,12 157.17,12 | 117,7 117,11 JP7.12 | 117,7 C8.+
  Top 0.406: C7.1 163.45,16.45 162,15 159,15 V12_1.1 | V12_1.1 R13.2 | D9.K 155,17 V12_1.1
  Top 0.6: 113.45,68 C15.1 | 109,82 D10.A | 109,82 110,81 110.46,81.46 U2.1 111,80 v111,79 | C14.1 108,81 109,82 | 1LODRV.8 1LODRV.1 109.69,68 113.45,68 | 115,68 113.45,68 | 115,68 117,68 | U1.1 116.4,30.6 D8.A 116,24.6 v116,24 | C16.1 v116,41 112.69,41 2LODRV.1 2LODRV.8 | v116,66 115,68 | IC1.8 115.69,60 v116,61 | V12_2.1 158,4 115.91,4 IC2.3 | v116,52 114,52
  Bottom 0.6: 116.38,23.62 v116,24 | v116,61 v116,66 116,74 v111,79
  Bottom 1: JP7.12 116.38,23.62 | v116,24 v116,41 116,50 v116,52 v116,61
  pour Top (isolate 2): 164,18 164,12 155,12 155,17 162,17
VB1
  Top 0.6: 1HDRV.1 115.64,97.09 C11.1 | D10.K 111.6,91.4 | U2.8 112,88.27 112,91 111.6,91.4 | 111.6,91.4 1HDRV.1 | 1HDRV.1 1HDRV.8 | 1HDRV.8 106.09,97.09 106,97 106.31,97 1HDRV.8
VB2
  Top 0.254: C12.1 108,29 109.19,29 | 109,28 109.19,28 D8.K | 2HDRV.8 109,20 109,24 2HDRV.1
  Top 0.6: U1.8 109.19,29 109.19,28 109.19,25.89 2HDRV.1
VDD  (1 unrouted)
  Top 0.6: JP7.14 111.3,8.77 C6.+ | IC2.1 109.53,7 C6.+ | NTC.2 106.73,4.73 108,6 108,7 109.27,7 C6.+
VFB
  Top 0.406: R7.1 98,5 99,6 99,10 103,14 108,14 109,13 109,11.24 JP7.15
  Top 0.6: JP7.15 110.76,14.76 111,16 111,15.9 C10.1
